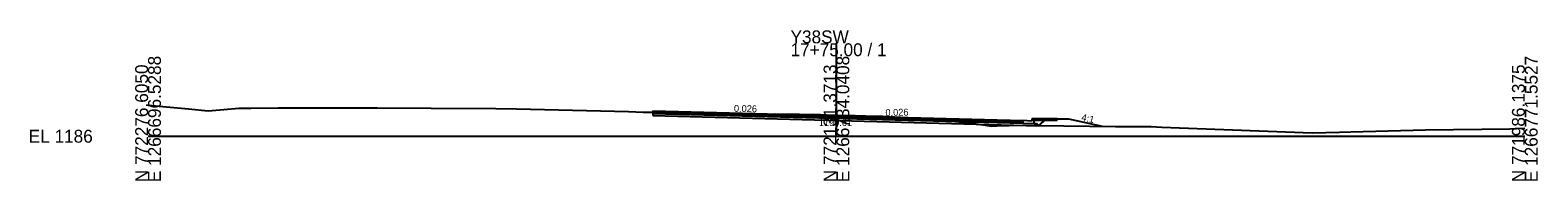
# Model space of a CAD drawing. Extents: x -26 to 3903, y -10 to 9504.
# Drawn here: x 3574.3 to 3902.8, y -9.7 to 23.1 of the extents above; entities that cross this region are included whole.
import ezdxf

# ---------------------------------------------------------------- set-up
doc = ezdxf.new("R2010")
doc.units = 0
for name, color, linetype in [('Exist Cross Section Cell', 7, 'Continuous'), ('Exist XS Center Line Elevation Label', 7, 'Continuous'), ('Exist XS Ground Line', 7, 'Continuous'), ('Prop CMT Pvmt Course 1', 7, 'Continuous'), ('Prop CMT Pvmt Course 2', 7, 'Continuous'), ('Prop CMT Pvmt Course 3', 7, 'Continuous'), ('Prop CMT Pvmt Course 4', 7, 'Continuous'), ('Prop CMT Shld Paved Course 1', 7, 'Continuous'), ('Prop CMT Slope Fill', 7, 'Continuous'), ('Prop CMT Slope Grass', 7, 'Continuous'), ('Prop CMT Subgrade Earthwork', 7, 'Continuous'), ('Prop Conc 4in Sidewalk', 7, 'Continuous'), ('Prop Conc Curb and Gutter', 7, 'Continuous'), ('Prop XS Ditch Slope Text', 7, 'Continuous'), ('Prop XS Finish Grade', 7, 'Continuous'), ('Prop XS SE Text', 7, 'Continuous')]:
    doc.layers.add(name, color=color, linetype=linetype)

msp = doc.modelspace()

# ---------------------------------------------------------------- linework, layer by layer
at = {"layer": 'Exist Cross Section Cell'}
for p, q in [((3750, 0), (3750, 20.21)), ((3600, 0), (3750, 0)), ((3750, 0), (3900, 0))]:
    msp.add_line(p, q, dxfattribs=at)
at = {"layer": 'Exist XS Ground Line'}
msp.add_lwpolyline([(3600, 6.74), (3608.78, 5.95), (3613.11, 5.52), (3616.51, 5.79), (3619.75, 6.07), (3622.41, 6.1), (3628.32, 6.15), (3634.9, 6.14), (3637.96, 6.15), (3641.59, 6.16), (3646.69, 6.17), (3649.93, 6.18), (3661.71, 6.11), (3675.78, 6.03), (3680.27, 5.93), (3704.7, 5.35), (3707.88, 5.21), (3710.77, 5.22), (3711.47, 5.21), (3712.97, 5.2), (3717.55, 5.12), (3736.14, 4.81), (3736.67, 4.88), (3741.98, 4.83), (3745.6, 4.75), (3746.16, 4.74), (3746.51, 4.7), (3747.85, 4.67), (3750, 4.61), (3754.09, 4.5), (3758.68, 4.39), (3760.08, 4.33), (3771.67, 3.69), (3774.97, 3.3), (3777.46, 3.06), (3778.29, 2.9), (3780.47, 2.7), (3783.84, 2.21), (3784.99, 2.27), (3787.64, 2.33), (3788.26, 2.38), (3810.83, 2.15), (3817.24, 2.1), (3817.97, 2.08), (3818.28, 2.09), (3818.58, 2.09), (3820.89, 1.99), (3853.64, 0.74), (3859.65, 0.85), (3862.08, 0.93), (3878.33, 1.38), (3896.76, 1.61), (3898.17, 1.65), (3900, 1.73)], dxfattribs=at)
at = {"layer": 'Prop CMT Pvmt Course 1'}
for p, q in [((3709.99, 5.27), (3749.99, 4.23)), ((3710, 5.52), (3790.6, 3.42)), ((3710, 5.27), (3790.6, 3.17)), ((3790.6, 3.17), (3790.6, 3.42))]:
    msp.add_line(p, q, dxfattribs=at)
at = {"layer": 'Prop CMT Pvmt Course 2'}
msp.add_line((3790.6, 2.92), (3790.6, 3.17), dxfattribs=at)
at = {"layer": 'Prop CMT Pvmt Course 3'}
msp.add_line((3710, 4.94), (3790.6, 2.84), dxfattribs=at)
at = {"layer": 'Prop CMT Pvmt Course 4'}
for p, q in [((3710, 5.52), (3710, 4.48)), ((3793.1, 2.78), (3793.57, 2.77)), ((3794.02, 2.29), (3793.57, 2.77))]:
    msp.add_line(p, q, dxfattribs=at)
at = {"layer": 'Prop CMT Shld Paved Course 1'}
for p in [(3728.42, 4.05), (3728.44, 4.05)]:
    msp.add_line(p, (3728.44, 4.05), dxfattribs=at)
at = {"layer": 'Prop CMT Slope Grass'}
msp.add_line((3793.1, 3.79), (3795.76, 3.79), dxfattribs=at)
at = {"layer": 'Prop CMT Subgrade Earthwork'}
for p, q in [((3710, 5.22), (3710, 4.48)), ((3710, 4.48), (3794.02, 2.29)), ((3752.87, 3.38), (3752.86, 4.4)), ((3794.02, 2.29), (3795.76, 3.79))]:
    msp.add_line(p, q, dxfattribs=at)
at = {"layer": 'Prop Conc 4in Sidewalk'}
for p, q in [((3793.1, 3.79), (3793.09, 3.46)), ((3793.09, 3.46), (3798.11, 3.46)), ((3798.1, 3.79), (3793.1, 3.79)), ((3798.11, 3.46), (3798.1, 3.79))]:
    msp.add_line(p, q, dxfattribs=at)
at = {"layer": 'Prop Conc Curb and Gutter'}
for p, q in [((3792.58, 3.3), (3790.6, 3.42)), ((3790.6, 3.42), (3790.6, 2.85)), ((3792.6, 3.29), (3792.58, 3.3)), ((3792.61, 3.79), (3792.6, 3.79)), ((3792.6, 3.79), (3792.6, 3.3)), ((3792.6, 3.3), (3792.6, 3.29)), ((3793.1, 3.79), (3792.61, 3.79)), ((3793.1, 2.79), (3793.1, 3.79)), ((3790.6, 2.85), (3790.6, 2.84)), ((3790.6, 2.84), (3793.07, 2.78)), ((3793.07, 2.78), (3793.1, 2.78)), ((3793.1, 2.78), (3793.1, 2.79))]:
    msp.add_line(p, q, dxfattribs=at)
at = {"layer": 'Prop XS Finish Grade'}
for p, q in [((3795.76, 3.79), (3800.54, 3.79)), ((3800.54, 3.79), (3807.9, 2.18))]:
    msp.add_line(p, q, dxfattribs=at)

# ---------------------------------------------------------------- texts
at = {"layer": 'Exist Cross Section Cell'}
for s, p in [('Y38SW', (3740, 20.21)), ('17+75.00 / 1', (3740, 17.41)), ('EL 1186', (3574, -1.4))]:
    msp.add_text(s, height=2.8, dxfattribs=at).set_placement(p)
for s, p in [('E 1266696.5288', (3602.8, -10)), ('E 1266734.0408', (3752.8, -10)), ('E 1266771.5527', (3902.8, -10)), ('N 772276.6050', (3600, -10)), ('N 772131.3713', (3750, -10)), ('N 771986.1375', (3900, -10))]:
    msp.add_text(s, height=2.8, rotation=90, dxfattribs=at).set_placement(p)
at = {"layer": 'Exist XS Center Line Elevation Label'}
msp.add_text('1190.61', height=1.5, dxfattribs=at).set_placement((3746.16, 2.24))
at = {"layer": 'Prop CMT Slope Fill'}
for rotation, p in [(359.5415, (3721, 4.38)), (359.5415, (3723, 4.48)), (359.7147, (3790.6, 3.42)), (359.7147, (3792.6, 3.29))]:
    msp.add_text('X', height=0.00025, rotation=rotation, dxfattribs=at).set_placement(p)
for p in [(3724.44, 3.97), (3713.23, 2.23)]:
    msp.add_text('X', height=0.00025, dxfattribs=at).set_placement(p)
at = {"layer": 'Prop XS Ditch Slope Text'}
msp.add_text('4:1', height=1.5, rotation=347.9152, dxfattribs=at).set_placement((3803.29, 3.43))
at = {"layer": 'Prop XS SE Text'}
for rotation, p in [(358.5867, (3727.65, 5.32)), (1.1458, (3760.69, 4.39))]:
    msp.add_text('0.026', height=1.5, rotation=rotation, dxfattribs=at).set_placement(p)

doc.saveas('drawing.dxf')
